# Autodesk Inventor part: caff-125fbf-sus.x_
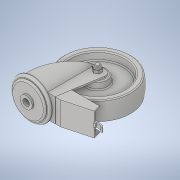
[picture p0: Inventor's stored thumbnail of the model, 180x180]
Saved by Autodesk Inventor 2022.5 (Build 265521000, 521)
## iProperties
Created: 2021-10
Part Number: caff-125fbf-sus.x_
Material: 一般
Document SubType Name: Modeling
Designer: ImaoCorp
Density: 1 g/cm^3
Appearance: 既定
Sending System: SOLIDWORKS 2019-2019304
MC: AMD64
MC_MODEL: Intel64 Family 6 Model 60 Stepping 3, GenuineIntel
OS: Windows_NT
FRU: Parasolid Version 31.0, build 290,  9- 1-2019
FORMAT: text
GUISE: transmit
KEY: caff-125fbf-sus
FILE: caff-125fbf-sus.x_t
DATE: Tue Oct 19 08:25:44 2021
Author: ImaoCorp
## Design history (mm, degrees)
feature "Base1"
node "ソリッド1"
